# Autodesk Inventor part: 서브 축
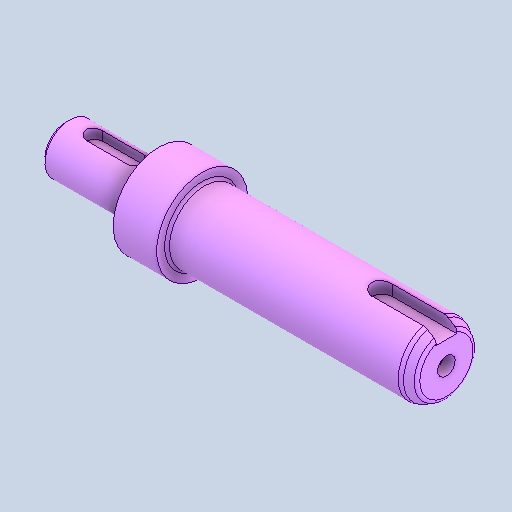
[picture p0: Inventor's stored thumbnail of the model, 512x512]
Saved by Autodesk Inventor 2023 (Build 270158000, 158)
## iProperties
Created: 2025-04
Part Number: 서브 축
Material: 강철, 탄소
Document SubType Name: Modeling
Designer: Admin
Density: 7.85 g/cm^3
Appearance: 기본값
Author: jhkim
Sending System: Autodesk Inventor 2026
Preprocessor: ST-DEVELOPER v20.1
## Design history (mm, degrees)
feature "솔리드1"
node "솔리드2"
